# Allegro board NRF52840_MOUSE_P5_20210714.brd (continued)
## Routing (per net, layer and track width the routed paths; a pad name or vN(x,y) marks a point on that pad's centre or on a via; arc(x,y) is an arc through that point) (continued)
VBAT_IN: length 31.6
  TOP w0.15: Q2604.2 15.15,34.15 R33.2 13.85,32.85 13.85,32.45 v1(13.7,32.3)
  LAYER3 w0.2: v1(13.7,32.3) 13.71,32.29 13.71,32.01 13.3,31.6 13.3,25.55 13.95,24.9 13.95,21.25 16.25,18.95 29.56,18.95 J9.1
  vias: v1(31,27.75) v1(31.05,27.05) v1(31.7,27.1) v1(32.3,27.1)
VBAT_OUT: length 3
  TOP w0.25: U1407.1 15.1,19.2 14.7,18.8 13.65,18.8 13.2,19.25 U1407.3
  vias: v1(16.75,22.15) v1(17.3,21.75) v1(17.8,22.2) v1(17.85,21.35) v1(28.7,24.7) v1(29.15,25.3) v1(29.6,24.7) v1(29.9,25.3)
VBUS: length 1.6
  BOTTOM w0.5: v1(21.7,79.3) 21.7,79.15 21.54,78.99 21.54,77.87 21.53,77.85 J1.1
  vias: v1(21.2,79.45)
VBUS_NRF: length 45.5
  TOP w0.25: v1(33.75,50.85) U1409.1
  TOP w0.4: U1.AD2 17.75,51.8 33.65,51.8 v1(33.7,51.75)
  LAYER3 w1: 29.77,80.83 30.5,80.1 30.5,79.33 36.32,73.5 36.32,59.67 35.68,59.03
  BOTTOM w0.15: v1(33.31,45.25) 33.29,45.05 32.89,44.75 TP6.1 32.33,45.01 33.26,45.63 v1(33.3,45.8)
  vias: v1(28.17,81.33) v1(28.62,80.9) v1(29.07,81.33) v1(33.3,35.45) v1(33.3,34.8) v1(33.3,34.15) v1(33.35,44.65)
VDD: length 134.7
  TOP w0.15: 30.7,43.4 30.7,42.95 v1(30.15,42.4) ; 16.88,55.68 U1.AD14
  TOP w0.2: 17.35,55.95 17.08,55.68 16.88,55.68 ; U1.Y2 15.62,52.52 15.85,52.3 15.85,52.15
  TOP w0.25: U1.W1 15.38,51.65 ; v1(30.05,32.2) 29.9,32.35 28.95,32.35 R44.2 R45.2 ; U1.A22 9.98,57.68 9.8,57.5 9,57.5 v1(8.95,57.45)
  TOP w0.3: R2.2 21.65,57.65 v1(21.67,57.63) ; 18.35,56.3 18,55.95 17.35,55.95 ; v1(30.65,42) 30.5,41.85 C61.1 30.5,40.55 ; C12.1 v1(8.95,57.45) ; U1.AD23 17.43,58.18 17.7,58.45 19.7,58.45 C8.1 20.15,58 20.15,57.53 v1(20.17,57.5)
  TOP w0.35: 18.35,56.3 18.8,56.75 C7.1 19.95,56.85 19.95,57.28 v1(20.17,57.5)
  TOP w0.4: v1(9.35,50.3) 9.81,50.76 9.81,50.81 10.88,51.88 U1.B1
  TOP w0.5: v1(9.35,50.3) 9.05,50 C14.1 ; v1(14.07,40.97) 14.55,40.5 14.55,40.25 C62.1 15.1,39.7 R23.2 ; R21.2 R22.2
  TOP w0.6: R21.2 6.2,53.1 v1(6.17,53.07)
  LAYER3 w0.35: v1(30.7,49.7) 30.7,49.9 27.5,53.1 26.05,53.1 21.67,57.47 v1(21.67,57.63) 20.3,57.63 v1(20.17,57.5)
  LAYER3 w0.4: v1(8.95,57.45) 8.9,57.45 8.85,57.5 8.12,57.5 6.17,55.55 v1(6.17,53.07)
  LAYER3 w0.5: v1(30.7,49.7) 30.75,49.65 30.75,44.2 30.05,43.5 ; 30.05,26.75 v1(30.05,32.2) 30.05,43.5 ; 30.05,43.5 30.1,43.45 ; 7.45,49.8 7.62,49.62 8.67,49.62 v1(9.35,50.3)
  LAYER3 w0.58: 11.4,44 11.4,44.65 15.4,48.65 v1(15.4,49.35)
  LAYER3 w0.6: 7.45,46.3 7.45,49.8 6.17,51.07 v1(6.17,53.07)
  LAYER3 w0.8: 8.5,44 11.4,44 11.4,43.65 v1(14.07,40.97) 14.55,40.5 14.55,34.65 15.25,33.95 15.25,22.05 16.95,20.35 28,20.35 30.9,23.25 30.9,25.9 30.05,26.75
  BOTTOM w0.5: TP7.1 32.08,49.7 v1(30.7,49.7)
  vias: v1(7.15,44.1) v1(7.45,44.8) v1(7.85,44.1) v1(14.7,41) v1(15.4,50.05)
VDD_LED: length 16.2
  TOP w0.2: U1401.3 11.75,45.35 12.25,44.85 12.25,44 11.85,43.6 11.7,43.6 U1401.1
  TOP w0.25: LED1.4 v1(22.58,12.32)
  LAYER3 w0.25: v1(22.58,12.32) 22.58,10.93 21.1,9.45 20.15,9.45 15.65,13.95 v1(15.65,15.35)
  LAYER3 w0.3: 14.75,16.65 14.4,17
  vias: v1(10.1,42.15) v1(10.1,41.45) v1(10.55,42.45) v1(10.9,41.95) v1(14.95,15.15) v1(15.55,16.15)
BAT_ADC: length 15
  TOP w0.1: 13.12,52.4 13.12,51.75
  TOP w0.15: 13.13,51.75 13.13,51.47 13.6,51 C34.1 13.4,45.85 12.9,45.35 12.9,43.25 12.1,42.45 12.1,40.45 12.75,39.8 R32.2 R31.1 ; U1.K2 13.12,52.4
BAT_MON_EN: length 29.5
  TOP w0.15: v1(16.2,28.05) 16.05,28.05 15.6,27.6 R34.2 14,28 13.4,28.6 U1408.1 ; v1(14.3,45.6) 14.1,45.8 14.1,46.35 13.9,46.55 13.9,51.2 13.45,51.65 13.45,52.11 U1.L1
  LAYER3 w0.15: v1(14.3,45.6) 15.25,44.65 15.25,35.1 15.9,34.45 15.9,28.2 16.05,28.05 v1(16.2,28.05)
BTN_LEFT: length 30.6
  TOP w0.15: U1.A12 9.78,55.18 8.8,54.2 8.5,54.2 v1(8.35,54.05)
  LAYER3 w0.15: v1(8.35,54.05) 8.6,54.05 10.15,55.6 13.2,55.6 14.15,56.55 14.15,66.1 11.95,68.3 11.95,70.85 11.04,71.75 J4.1
BTN_PCB_AIM: length 60.7
  TOP w0.15: J5.6 36.05,25.35 34.85,25.35 34.4,24.9 34.4,22.1 v1(34.77,21.73) ; v1(13.25,36.1) 13.25,36.8 12.1,37.95 12.1,39.95 11.8,40.25 11.8,42.65 12.6,43.45 12.6,45.95 13.3,46.65 13.3,50.65 12.8,51.15 12.8,52.11 U1.J1
  LAYER3 w0.15: v1(34.77,21.73) 34,20.95 30.9,20.95 29.3,19.35 16.4,19.35 14.3,21.45 14.3,25.15 13.7,25.75 13.7,31.45 14.25,32 14.25,32.6 13.7,33.15 13.7,35.65 v1(13.25,36.1)
BTN_PCB_BACK: length 48.4
  TOP w0.15: v1(35,24.35) 35.1,24.45 J5.4 ; U1.AD18 17.05,56.68 17.47,57.1
  TOP w0.2: v1(18.9,57.85) 18.9,57.77 18.22,57.1 17.47,57.1
  LAYER3 w0.15: v1(35,24.35) 35,24.45 35.1,24.55 35.1,25.3 34.3,26.1 34.3,26.8 31.4,29.7 31.4,36.05 30.8,36.65 30.8,41.25 31.3,41.75 31.3,51.78 24.93,58.15 19.2,58.15 v1(18.9,57.85)
BTN_PCB_FRONT: length 50.2
  TOP w0.15: J5.5 38.5,24.95 37.3,26.15 35.2,26.15 34.85,26.5 v1(34.85,26.55)
  TOP w0.2: v1(18.17,57.88) 17.75,57.45 17.3,57.45 17.03,57.18 U1.AD20
  LAYER3 w0.15: v1(18.17,57.88) 18.17,58 18.62,58.45 25.07,58.45 31.7,51.83 31.7,41.6 31.15,41.05 31.15,36.8 31.7,36.25 31.7,29.9 34.85,26.75 v1(34.85,26.55)
BTN_RIGHT: length 53.9
  TOP w0.1: 9.53,56 9.78,56 9.85,55.93 10.6,55.93
  TOP w0.15: 9.53,56 8,56 7.55,55.55 v1(7.55,55.02) ; J6.1 35,67.28 35,61.05 26.68,52.73 26.68,52.52 v1(26.75,52.45) ; 10.6,55.93 U1.B15
  LAYER3 w0.15: v1(7.55,55.02) 7.5,54.98 7.5,53.45 8.1,52.85 9.85,52.85 11.4,54.4 13.9,54.4 15.38,55.88 16.03,55.88 17.2,57.05 19.45,57.05 24.6,51.9 26.2,51.9 v1(26.75,52.45)
BTN_WHEEL: length 47.2
  TOP w0.14: 9.53,55.68 U1.A14
  TOP w0.15: 9.53,55.68 9.08,55.68 8.75,55.35 8.47,55.35 v1(8.35,55.47)
  TOP w0.25: J7.1 34.6,67.22 34.6,61.25 25.95,52.6 v1(25.95,52.45)
  LAYER3 w0.15: v1(25.95,52.45) 25.7,52.2 24.75,52.2 19.6,57.35 17.05,57.35 15.93,56.22 15.28,56.22 13.75,54.7 11.2,54.7 10.45,53.95 10.45,53.9 9.75,53.2 8.2,53.2 7.85,53.55 7.85,54.5 8.07,54.72 8.07,55.2 v1(8.35,55.47)
D_N: length 47
  TOP w0.175: v1(28.72,79.62) 28.95,79.4 29.67,79.4 ; 29.67,79.4 30.37,79.4 31.42,78.35 31.42,60.22 24.47,53.27 16.97,53.27 U1.AD4 ; 29.67,79.4 D3.1
  BOTTOM w0.175: v1(28.72,79.62) 28.52,79.42 22.87,79.42 22.42,78.97 22.42,78.6 22.21,78.39 J1.2
D_P: length 45.9
  TOP w0.175: v1(28.72,78.83) 28.72,78.95 28.9,79.12 29.67,79.12 ; 29.67,79.12 D2.1 ; 29.67,79.12 30.26,79.12 31.15,78.24 31.15,60.34 24.36,53.55 17,53.55 U1.AD6
  BOTTOM w0.175: J1.3 22.97,77.87 22.97,78.35 22.7,78.62 22.7,78.86 22.99,79.15 28.5,79.15 28.72,78.92 v1(28.72,78.83)
DEC1: length 2.8
  TOP w0.15: C5.1 10.2,50.43 11.38,51.6 U1.C1
DEC3: length 2.4
  TOP w0.15: U1.D23 11.5,58.31 11.5,58.6 10.92,59.17 10.72,59.17 10.2,59.7 C11.1
DEC4_6: length 15.7
  TOP w0.25: v1(11,59.75) 11,59.6 11.87,58.73 U1.E24 ; U1.B5 10.33,53.43
  TOP w0.35: 10.33,53.43 9.75,52.85
  TOP w0.5: 9.75,52.85 C15.2
  LAYER3 w0.25: 7.35,56 6.89,55.54 6.89,53.51 7.65,52.75 v1(7.65,51.62) ; v1(11,59.75) 11.15,59.6 11.15,59.35 11.6,58.9 11.6,57.9 10.5,56.8
  LAYER3 w0.3: 10.5,56.8 8.15,56.8 7.35,56
LED_B: length 19.2
  TOP w0.1: 15.12,58.92 15.13,58.43
  TOP w0.15: v1(30.3,55.35) 30.95,54.7 U1405.1 ; 15.13,58.93 15.13,59.03 15.45,59.35 16,59.35 16.4,59.75 17.4,59.75 v1(17.5,59.85) ; 15.13,58.43 U1.V23
  LAYER3 w0.15: v1(30.3,55.35) 29.65,55.35 25.3,59.7 17.65,59.7
  LAYER3 w0.2: 17.65,59.7 v1(17.5,59.85)
LED_G: length 56.4
  TOP w0.1: 14.62,58.43 14.62,59.05 14.68,59.11
  TOP w0.15: v1(15.8,59.9) 15.47,59.9 14.68,59.11 ; v1(33,22) 32.1,22 U1404.1 ; 14.62,58.43 U1.T23
  LAYER3 w0.15: v1(15.8,59.9) 15.95,59.9 16.8,59.05 24.98,59.05 32.07,51.95 32.07,43.32 32.6,42.8 32.6,36.7 32.07,36.17 32.07,30.08 35.55,26.6 35.55,23.9 33.65,22 v1(33,22)
LED_R: length 83
  TOP w0.1: 14.13,58.43 14.13,58.49 14.12,59
  TOP w0.15: v1(16.5,60.25) 16.5,60.35 16.34,60.51 15.11,60.51 14.13,59.53 14.13,59 ; 14.13,58.43 U1.P23
  TOP w0.25: U1403.1 15.05,25.85 v1(14.4,25.85)
  LAYER3 w0.15: v1(14.4,25.85) 14.45,25.85 14.6,25.7 14.6,21.65 16.55,19.7 29,19.7 30.6,21.3 33.55,21.3 35.9,23.65 35.9,26.7 32.4,30.2 32.4,35.95 32.9,36.45 32.9,43.1 32.4,43.6 32.4,52.13 25.18,59.35 17.1,59.35 16.5,59.95 v1(16.5,60.25)
MISO: length 14.5
  TOP w0.15: v1(18.1,54.4) 18.06,54.4 17.85,54.61 16.94,54.61 U1.AD10 ; U2.12 17.58,43.87 16.65,44.8 16.65,46.25 16.1,46.8 v1(16.1,47.45) 16,47.45 R30.1
  LAYER3 w0.15: v1(18.1,54.4) 18,54.3 18,52.3 16.25,50.55 16.25,47.6 v1(16.1,47.45)
MOSI: length 13.3
  TOP w0.15: U1.AD12 17.43,55.18 17.5,55.25 18.5,55.25 18.97,54.77 19.07,54.77 v1(19.15,54.7)
  LAYER3 w0.15: U2.11 17.58,45.77 16.6,46.75 16.6,50.4 18.35,52.15 18.35,53.85 19.05,54.55 19.05,54.6 v1(19.15,54.7)
MOTION: length 12.7
  TOP w0.1: 17.22,56.43 16.5,56.43
  TOP w0.15: v1(17.7,56.55) 17.58,56.43 17.22,56.43 ; 16.5,56.43 U1.AC17
  LAYER3 w0.15: v1(17.7,56.55) 17.8,56.65 19.4,56.65 20.7,55.35 20.7,53.3 17.8,50.4 17.8,49.13 U2.9
NCHRG: length 45
  TOP w0.15: U1.N1 13.87,51.72 14.25,51.35 14.25,46.85 14.6,46.5 v1(14.6,46.3) ; v1(28.8,30) 28.9,30.1 R45.1 29.9,30.65 U1406.1
  LAYER3 w0.15: v1(28.8,30) 28.65,29.85 28.65,26.85 27.85,26.05 24.55,26.05 24.25,25.75 18.35,25.75 17.24,26.85 17.24,34.25 16.02,35.47 16.02,45.07 15.5,45.6 15.5,46.1 15.3,46.3 v1(14.6,46.3)
NSTDBY: length 51.3
  TOP w0.1: 14.12,51.92 14.12,52.4
  TOP w0.15: U1406.5 31.3,33.35 30.8,32.85 29.15,32.85 R44.1 29.3,33.5 v1(29.3,33.6) ; 14.12,52.4 U1.P2 ; 14.13,51.92 14.55,51.5 14.55,47.15 15.3,46.4 15.3,46.05 15,45.75 v1(15,45.7)
  LAYER3 w0.15: v1(15,45.7) 15.05,45.65 15.05,45.5 15.65,44.9 15.65,35.35 16.92,34.08 16.92,26.63 18.1,25.45 24.45,25.45 24.75,25.75 28.05,25.75 29.05,26.75 29.05,29.35 29.35,29.65 29.35,33.55 v1(29.3,33.6)
PMW_RESET: length 58
  TOP w0.15: U1.U1 14.87,47.45 16.05,46.28 v1(16.05,45.9)
  LAYER3 w0.15: U2.7 28.28,46.02 29.5,44.8 29.5,34.55 28.77,33.82 28.77,30.77 28.3,30.3 28.3,27.1 27.6,26.4 24.45,26.4 24.1,26.05 18.5,26.05 17.55,27 17.55,34.4 16.35,35.6 16.35,45.6 v1(16.05,45.9)
PWM_CS: length 14.6
  TOP w0.15: U1.AD8 16.89,54.2 17.32,54.2 v1(17.39,54.13)
  LAYER3 w0.15: v1(17.39,54.13) 17.6,53.92 17.6,52.4 15.95,50.75 15.95,48.35 15.6,48 15.6,47.15 16.7,46.05 16.7,43 17.58,42.12 U2.13
RESET: length 20.3
  TOP w0.1: 16.57,55.43 17.28,55.43 17.4,55.55
  TOP w0.15: v1(23.55,57.2) 23.55,57.4 22.8,58.15 R2.1 22.3,58 22.3,57.25 C27.2 21.85,56.85 21.2,56.2 19.55,56.2 19.45,56.3 18.95,56.3 18.2,55.55 17.4,55.55 ; 16.57,55.43 U1.AC13
  BOTTOM w0.15: TP5.1 32.3,52.54 32.3,52.54 32.3,52.95 31.6,53.65 27.35,53.65 23.8,57.2 v1(23.55,57.2)
SCLK: length 13.1
  TOP w0.1: 16.5,54.93 17.48,54.93 17.5,54.91
  TOP w0.15: 16.5,54.93 U1.AC11 ; U2.10 17.58,47.52 16.65,48.45 16.65,49.4 17.25,50 v1(17.25,50.2) ; v1(19.8,54.27) 19.67,54.15 18.85,54.15 18.65,54.35 18.65,54.57 18.31,54.91 17.5,54.91
  LAYER3 w0.15: v1(17.25,50.2) 17.25,50.55 18.7,52 18.7,53.75 19.1,54.15 19.67,54.15 v1(19.8,54.27)
SWDCLK: length 17.5
  TOP w0.15: v1(27.7,59.35) 16.5,59.35 15.87,58.72 U1.AA24
  BOTTOM w0.15: TP3.1 29.81,57.53 28,59.35 v1(27.7,59.35)
SWDIO: length 18.9
  TOP w0.15: U1.AC24 16.38,58.68 16.7,59 22.6,59 24.1,57.5 v1(24.25,57.5)
  BOTTOM w0.15: TP2.1 32.3,54.6 31.7,54 27.5,54 24.25,57.25 v1(24.25,57.5)
WHELL_A: length 25.5
  TOP w0.1: 9.53,55.33 9.63,55.43 10.6,55.43
  TOP w0.15: v1(13.65,64.6) 13.7,64.6 13.85,64.75 13.85,66.4 12.3,67.95 12.3,68.7 13.86,70.26 J3.2 ; 9.53,55.33 9.43,55.33 8.86,54.76 8.64,54.76 v1(8.6,54.8) 8.3,54.8 7.65,54.15 R22.1 ; U1.B13 10.6,55.43
  LAYER3 w0.15: v1(13.65,64.6) 13.65,64.57 13.85,64.37 13.85,56.7 13.05,55.9 10,55.9 9.55,55.45 9.1,55.45 8.6,54.95 v1(8.6,54.8)
WHELL_B: length 23
  TOP w0.1: 10.6,54.93 9.98,54.93 9.75,54.7
  TOP w0.15: R21.1 7.55,53.15 7.92,53.52 8.82,53.52 v1(9.05,53.75) 9.05,54 9.75,54.7 ; U1.B11 10.6,54.93
  LAYER3 w0.15: v1(9.05,53.75) 9.05,54 10.35,55.3 13.4,55.3 14.45,56.35 14.45,67.63 J3.1
WHELL_COM: length 25.3
  TOP w0.1: 9.85,54.25 10.03,54.43 10.6,54.43
  TOP w0.15: U1.B9 10.6,54.43 ; 9.85,54.25 9.75,54.15 v1(9.75,53.95)
  LAYER3 w0.15: J3.3 15.25,71.83 15.25,67.5 14.75,67 14.75,56.2 13.55,55 10.6,55 9.75,54.15 v1(9.75,53.95)
XC1: length 5
  TOP w0.15: U1.B24 10.47,58.68 9.35,59.8 C1.1 9.05,59.65 7.3,59.65 6.77,60.18 X1.1
XC2: length 2.8
  TOP w0.15: U1.A23 9.56,59 C2.1 8,59 X1.3
N00013: length 2.2
  TOP w0.15: U1.N24 13.8,58.75 13.8,59.7 14.3,60.2 C9.1
N00015: length 5.3
  TOP w0.184: v1(16.2,53.85) 16.2,53.61 U1.AC5
  TOP w0.3: C20.1 19.6,55.7 19.25,55.7 v1(19.2,55.75)
  LAYER3 w0.25: v1(19.2,55.75) 19.15,55.7 17.6,55.7 16.2,54.3 v1(16.2,53.85)
N00024: length 1.4
  TOP w0.5: L3.2 6.78,50.82 6.78,50.33 6.77,50.33 6.77,49.5
N00025: length 4.6
  TOP w0.25: 10.62,52.68 U1.B3
  TOP w0.4: 9.95,52 9.95,52.05 10.58,52.68 10.62,52.68
  TOP w0.5: L2.2 8.07,50.12 9.95,52
N00047: length 5.8
  TOP w0.15: X2.1 10.32,48.18 11,48.85 C17.1 11.05,48.95 11.5,49.4 11.5,50.55 11.74,50.79 11.74,52.57 U1.D2
N00048: length 6
  TOP w0.12: U1.F2 12.03,52.58 12.03,51.79 12.04,51.78
  TOP w0.15: 12.2,49.1 C18.1 ; 12.2,49.1 12.15,49.1 11.8,49.45 11.8,50.4 12.04,50.64 12.04,51.78 ; 12.2,49.1 11.55,48.45 11.55,47.72 X2.2
N00074: length 3.3
  TOP w0.15: U1.H23 12.52,58.28 12.52,59.08
  TOP w0.293: 12.52,59.08 C25.1 12.52,60.7 L4.1
N00235:
  vias: v1(18.3,77.85) v1(18.6,79.1) v1(18.9,78.55) v1(19.45,79.3) v1(19.8,78.5) v1(25.25,77.55) v1(27.5,78.3) v1(27.5,77.45)
N379055: length 13.2
  TOP w0.25: LED1.1 22.57,13.83 18.8,17.6 18.8,22.55 17.45,23.9 R24.2
N379073: length 10.6
  TOP w0.25: R25.2 28.1,18.5 23.53,13.93 LED1.2
N379080: length 57.8
  TOP w0.2: v1(31.25,56.25) 31.35,56.35 R26.2
  TOP w0.25: LED1.3 v1(23.53,12.33)
  LAYER3 w0.2: v1(23.53,12.33) 23.53,13.73 25.2,15.4 32.8,15.4 33.95,16.55 33.95,18.75 36.3,21.1 36.3,26.85 32.75,30.4 32.75,35.7 33.3,36.25 33.3,43.2 32.75,43.75 32.75,53.95 31.25,55.45 v1(31.25,56.25)
N379134: length 3.2
  TOP w0.25: R24.1 16.65,24.7 15.75,23.8 U1403.3
N379451: length 1.6
  TOP w0.25: U1404.3 R25.1
N379621: length 2.8
  TOP w0.2: U1405.3 33.25,55.8 R26.1
N384910: length 1.5
  TOP w0.15: U1406.6 30.1,33.95 30.1,35 R27.2
N404039: length 4
  TOP w0.15: Q2604.1 13.2,34.4 R33.1 13.2,31.85 13.75,31.3 U1408.3
N404214: length 2.2
  TOP w0.15: Q2604.3 14.05,36.65 12.8,37.9 R31.2
N445725: length 24.7
  TOP w0.25: v1(33.95,43.75) 33.95,46.9 32.2,48.65 U1409.3 ; v1(34,30.05) 34,29.85 R43.1 33.6,29.45 33.6,27.25 32.35,26 Q2605.1
  LAYER3 w0.25: v1(34,30.05) 34,43.7 v1(33.95,43.75)
N454705: length 2
  TOP w0.293: 11.4,61.83 10.72,62.51 C26.1 10.58,62.65 C58.1
N455919: length 2
  TOP w0.293: 8.05,63.7 C59.1 C58.2
  vias: v1(1.5,79.47) v1(1.5,78.7) v1(2,63.65) v1(2.4,64.1) v1(2.8,63.65) v1(3.2,64.1) v1(3.55,63.65) v1(3.9,64.1)

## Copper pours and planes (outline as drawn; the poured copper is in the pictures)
GND on TOP: 20.32,3.35 15.54,3.96 10.9,5.3 10.9,38.22 5.68,42.16 5.68,47.56 4.5,49.7 4.5,61.8 7.75,61.8 7.75,61.95 9.15,61.95 9.15,63.3 9.1,63.35 8.85,63.35 8.85,63.95 9.2,64.3 10.17,64.3 10.45,64.58 10.45,82.59 12.23,83.08 17.1,83.08 17.1,81.88 28.7,81.88 28.7,83.08 33.57,83.08 42.3,80.68 42.3,64.67 41.4,64.67 41.4,57.07 36.98,57.07 34.9,55 34.9,29.3 40.75,29.3 40.75,18.72 34.9,18.72 34.9,6.13 29.32,4.2 23.48,3.35
GND on BOTTOM: 20.32,3.35 15.54,3.96 10.9,5.3 10.9,38.22 5.68,42.16 5.68,47.56 4.5,49.7 4.5,61.8 7.75,61.8 7.75,64 8.05,64.3 10.05,64.3 10.45,64.7 10.45,82.59 12.23,83.08 17.1,83.08 17.1,81.88 28.7,81.88 28.7,83.08 33.57,83.08 42.3,80.68 42.3,64.67 41.4,64.67 41.4,57.07 36.98,57.07 34.9,55 34.9,29.3 40.75,29.3 40.75,18.72 34.9,18.72 34.9,6.13 29.32,4.2 23.48,3.35 ; 1 cut-out
GND on BOTTOM: 9.44,75.54 10.28,75.54 10.62,75.03 11.21,74.82 11.54,74.82 11.54,74.04 9.44,74.04
GND on LAYER2: 20.32,3.35 15.54,3.96 10.9,5.3 10.9,38.22 5.68,42.16 5.68,47.56 4.5,49.7 4.5,61.8 7.75,61.8 7.75,64 8.05,64.3 9.3,64.3 10.45,65.45 10.45,82.59 12.23,83.08 17.1,83.08 17.1,81.88 28.7,81.88 28.7,83.08 33.57,83.08 42.3,80.68 42.3,64.67 41.4,64.67 41.4,57.07 36.98,57.07 34.9,55 34.9,29.3 40.75,29.3 40.75,18.72 34.9,18.72 34.9,6.13 29.32,4.2 23.48,3.35
GND on LAYER3: 20.32,3.35 15.54,3.96 10.9,5.3 10.9,38.22 5.68,42.16 5.68,47.56 4.5,49.7 4.5,61.8 7.75,61.8 7.75,64 8.05,64.3 10.05,64.3 10.45,64.7 10.45,82.59 12.23,83.08 17.1,83.08 17.1,81.88 28.7,81.88 28.7,83.08 33.57,83.08 42.3,80.68 42.3,64.67 41.4,64.67 41.4,57.07 36.98,57.07 34.9,55 34.9,29.3 40.75,29.3 40.75,18.72 34.9,18.72 34.9,6.13 29.32,4.2 23.48,3.35
VBAT_IN on TOP: 33.05,26.8 33.05,31.72 31.82,31.72 31.82,30.4 31.32,29.9 31.32,28.53 30.75,27.95 30.75,26.8
VBAT_IN on BOTTOM: 22.05,26 22.05,22.75 24.9,19.9 26.85,19.9 29.3,17.45 30.85,17.45 30.85,18.85 32.6,20.6 32.6,28.8 30.75,28.8 30.75,21.95 30.5,21.7 26.35,21.7 25.65,22.4 25.65,23.2 24.05,24.8 24.05,26
VBAT_OUT on TOP: 14.6,22.4 14.6,19.15 16.1,19.15 16.1,20.55 16.45,20.9 18.1,20.9 18.1,22.3 18,22.4
VBAT_OUT on TOP: 30.22,27.43 30.22,24.35 28.37,24.35 28.37,27.43
VBAT_OUT on BOTTOM: 24.8,26.4 24.8,25 24.95,24.85 27.85,24.85 27.85,24.4 30.3,24.4 30.3,26.4
VBAT_OUT on LAYER3: 16.55,21.65 16.55,22.75 26.8,22.75 28.02,23.98 28.02,24.73 28.85,25.55 30.25,25.55 30.25,23.6 27.6,20.95 17.25,20.95
VBUS on TOP: 21.27,79.08 20.95,79.4 20.95,80.6 21.8,81.45 23.45,81.45 23.45,80.55 22.4,80.55 21.95,80.1 21.95,79.15 21.87,79.08
VBUS on BOTTOM: 20.95,79.7 20.95,78.85 21.35,78.45 21.35,76.95 21.85,76.95 21.85,79.7
VBUS_NRF on TOP: 32,33.2 33.66,33.2 33.66,35.7 32.3,35.7 32.3,34.5 32,34.2
VBUS_NRF on TOP: 23.75,80.55 23.75,81.45 27.9,81.45 28.05,81.6 29.37,81.6 29.37,81.22 28.7,80.55
VBUS_NRF on BOTTOM: 32.3,45.95 32.3,33.85 33.55,33.85 33.55,45.95
VBUS_NRF on LAYER3: 27.97,81.58 27.97,80.58 29.32,80.58 30.05,79.85 30.76,80.56 29.75,81.58
VBUS_NRF on LAYER3: 33,44.25 33,57.05 35.82,59.88 36.52,59.17 34,56.65 34,44.75 33.5,44.25
VDD on TOP: 15.1,48.55 15.1,51.45 15.25,51.6 15.25,51.9 15.7,51.9 15.7,52.3 15.75,52.35 16,52.35 16,48.55
VDD on TOP: 9.4,43.1 9.4,43.85 9.05,44.2 8.45,44.2 8.1,44.55 8.1,45.1 6.85,45.1 6.85,43.1
VDD on TOP: 14,41.3 14,39.3 14.15,39.15 14.15,37.9 15.5,37.9 15.5,41.3
VDD on TOP: 27.7,43.35 27.7,42.2 29.15,42.2 29.4,41.95 29.4,41.6 29.2,41.4 27.9,41.4 27.9,40.15 31.95,40.15 31.95,41.85 32.65,42.55 32.65,44.15 29.6,44.15 28.8,43.35
VDD on LAYER3: 15,41.6 15,39.35 14.1,39.35 14.1,40.35 13.55,40.9 13.55,41.6
VDD on LAYER3: 8.8,44.4 10.05,44.4 10.05,43.6 7.27,43.6 6.9,43.97 6.9,45.27 7.15,45.52 7.15,46.72 7.75,46.72 7.75,45.45
VDD on LAYER3: 30.95,43.15 30.95,41.85 30.55,41.45 29.8,41.45 29.8,43.62 30.47,43.62
VDD_LED on TOP: 10.75,43.75 10.75,43.25 9.8,42.3 9.8,41.2 11.15,41.2 11.55,41.6 11.55,42.7 12,43.15 12,43.75
VDD_LED on TOP: 14.5,17.55 14.5,14.85 15.95,14.85 15.95,17.55
VDD_LED on LAYER3: 11.75,38.3 9.85,40.2 9.85,42.75 10.7,42.75 11.55,41.9 11.55,40.5 13.05,39 13.05,19.05 16,16.1 16,14.9 14.35,14.9 11.75,17.5
DEC4_6 on TOP: 9.55,53.1 9.55,52.6 8.75,52.6 8.05,51.9 8.05,50.7 7.4,50.7 7.4,52.65 7.8,52.65 8.25,53.1
N00235 on TOP: 19.7,80.7 18.1,80.7 18.1,77.1 28.15,77.1 28.15,78.12 27.67,78.6 25.9,78.6 25.1,77.8 20.7,77.8 20.45,78.05 20.45,78.85 19.7,79.6
N00235 on BOTTOM: 18.2,81.75 18.2,76.75 27.7,76.75 27.7,81.75
N372358 on TOP: 15.7,37.7 15.7,38.75 17.95,38.75 17.95,37.7
N372603 on TOP: 27.75,38.55 27.75,39.6 29,39.6 29.65,38.95 30.75,38.95 30.75,37.2 29.65,37.2 28.3,38.55
N455919 on TOP: 1.91,68.06 0.5,68.06 0.5,79.64 3.07,80.35 4.05,79.52 4.93,80.45 4.91,80.65 4.85,80.84 5.23,80.95 6.06,81.6 7.1,81.46 7.64,81.61 8.18,79.69 7.56,79.52 6.78,78.95 5.83,79.04 2.5,78.12 2.5,66.56 1.91,66.56
N455919 on TOP: 1.71,63.36 8.25,63.36 8.25,64.36 1.71,64.36
N455919 on BOTTOM: 2.71,68.36 8,68.36 8,65.3 9.5,65.3 9.5,69.86 2.71,69.86 2.71,74.04 8.35,74.04 8.35,75.54 2.71,75.54 2.71,79.03 5.47,79.03 6.42,78.7 7.37,79.03 9.5,79.03 9.5,81.53 7.32,81.53 6.61,81.33 6.7,79.24 5.72,81.08 0.3,79.59 0.3,67.86 1.71,67.86 1.71,63.36 4.2,63.36 4.2,65.36 2.71,65.36

Small or netless copper shapes (teardrops, artwork), in the pictures only: 1 on LAYER3

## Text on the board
Ref Des/Assembly Bottom: NRF52840_MOUSE_P5-20210714 | NRF52840_MOUSE_P5.
Ref Des/Silkscreen Bottom: REST | CLK | VDD | BAC | FRO | AIM | GND | VBUS | IO
Ref Des/Assembly Top: NRF52840_MOUSE_P5-20210714 | NRF52840_MOUSE_P5.
Ref Des/Silkscreen Top: 210714 | NRF52840 | MOUSE_P5.
BODY_CENTER: Panel Mode: | 1x2
1-DXF-TOP: 20170XXX-1 | XX_XXX_XX_P0
User.7: Soldermask | Top | L2 | L3 | Bottom | PREPEG | TOP | L4-BOT | Layer | L1-TOP | Impedance demand: | STACKUP:JLC7628 | single Impedance demand: | Impedance | 90+/-10% | 50+/-10% | diff | (ohm) | single | 4 | 1.0MM | 0.175/0.1 | (mm) | 0.2934 | WIDTH | WIDTH/SPACE | 0.2MM | 0.035MM | 0.465MM | 0.0175MM | REF. LAYER | Tg: | Notes: | Other Notes: | Board Name: | Drill Tolerance: | Min Width/Space: | Soldermask Color: | Silkscreen Color: | Surface Finished: | Input Gerber file: | Dielectric Material: | Compare With IPC File: | Min Drill  inner diameter: | NRF52840_MOUSE_P5. | PTH: | Layers: | FR-4 | 0.1mm | White | Green | Yes | RS-274-X | >= 140 C | Enig + OSP | 0.0762 mm | 0.0762/0.0762 mm | 0.2mm | NPTH: | Enig | 6x00 | No | black | Other | Blue | Hi-Tg | Board Thickness: | 170 | 0.1/ 0.1 mm | 0.0508 mm | C | 0.25mm | OSP | 1.0 | SLOT: | HASL | mm+/-0.1 mm | 0.3mm | 0.15 / 0.15 mm | 0.127 mm
User.8: VDD | REST | CLK | IO | FRO | BAC | AIM | GND | VBUS
User.14: FIGURE | SIZE | 0.3 | 0.7 | 1.0 | 1.1 | 0.6 | 0.75 | 1.5 | 1.54 | 1.6 | 2.5 | 2.5x1.3 | 4.6x4.2 | DRILL CHART: TOP to BOTTOM | ALL UNITS ARE IN MILLIMETERS | TOLERANCE | +0.0762/-0.0762 | +0.0508/-0.0508 | +0.127/-0.127 | PLATED | NON-PLATED | QTY | 613 | 18 | 3 | 6 | 2 | 4
